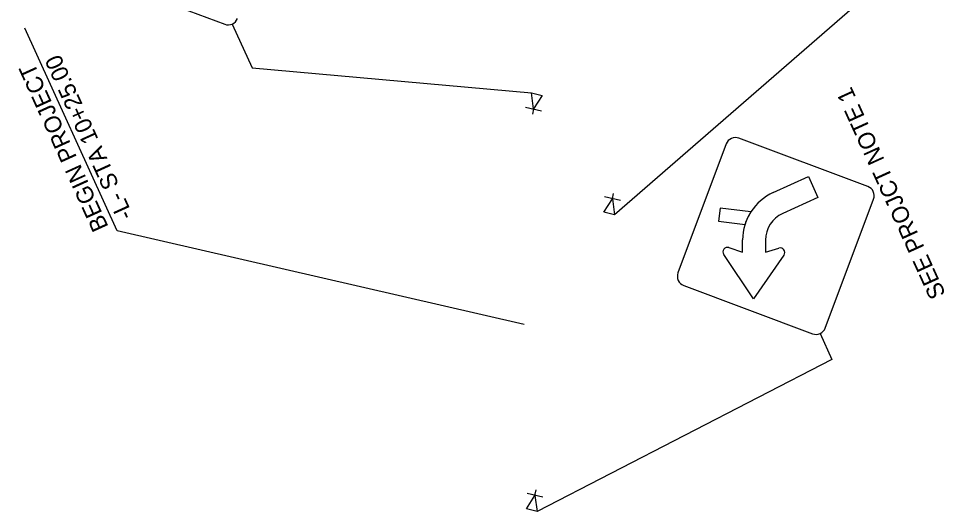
# Model space of a CAD drawing. Extents: x 2096093 to 2099001, y 683546 to 685907.
# Drawn here: x 2096431.2 to 2096816.5, y 683545.9 to 683750.8 of the extents above; entities that cross this region are included whole.
import ezdxf

# ---------------------------------------------------------------- set-up
doc = ezdxf.new("R2010")
doc.units = 0
for name, color, linetype in [('Default', 7, 'Continuous'), ('Exist Sign E Curve Left CELL', 7, 'Continuous'), ('Prop Horizontal Alignment Station Label', 7, 'Continuous')]:
    doc.layers.add(name, color=color, linetype=linetype)

msp = doc.modelspace()

# ---------------------------------------------------------------- linework, layer by layer
at = {"layer": 'Default'}
for p, q in [((2096645.33, 683713.23), (2096644.42, 683719.91)), ((2096644.42, 683719.91), (2096648.87, 683718.86)), ((2096648.87, 683718.86), (2096645.33, 683713.23)), ((2096641.99, 683714.02), (2096648.61, 683712.46)), ((2096645.33, 683713.23), (2096644.8, 683710.98)), ((2096678.06, 683675.89), (2096678.59, 683678.14)), ((2096674.52, 683670.25), (2096678.06, 683675.89)), ((2096681.4, 683675.11), (2096674.77, 683676.66)), ((2096678.06, 683675.89), (2096678.98, 683669.21)), ((2096678.98, 683669.21), (2096674.52, 683670.25)), ((2096764.44, 683619.87), (2096769.35, 683609.07)), ((2096645.88, 683552.62), (2096646.4, 683554.87)), ((2096642.34, 683546.98), (2096645.88, 683552.62)), ((2096649.22, 683551.84), (2096642.59, 683553.38)), ((2096645.88, 683552.62), (2096646.79, 683545.94)), ((2096646.79, 683545.94), (2096642.34, 683546.98))]:
    msp.add_line(p, q, dxfattribs=at)
for points in [[(2096775.78, 683769.09), (2096780.98, 683757.66), (2096678.98, 683669.21)], [(2096520.03, 683748.5), (2096528.29, 683730.35), (2096644.42, 683719.91)], [(2096769.35, 683609.07), (2096769.35, 683609.07), (2096646.79, 683545.94)]]:
    msp.add_lwpolyline(points, dxfattribs=at)
at = {"layer": 'Exist Sign E Curve Left CELL'}
for p, q in [((2096463.32, 683768.48), (2096516.91, 683748.4)), ((2096784.26, 683680.99), (2096730.67, 683701.07)), ((2096725.42, 683698.69), (2096705.34, 683645.1)), ((2096763.49, 683676.41), (2096748.87, 683669.77)), ((2096763.49, 683676.41), (2096748.87, 683669.77)), ((2096763.49, 683676.41), (2096748.87, 683669.77)), ((2096766.57, 683622.15), (2096786.65, 683675.74)), ((2096707.73, 683639.85), (2096761.32, 683619.76))]:
    msp.add_line(p, q, dxfattribs=at)
for points in [[(2096744.93, 683678.44), (2096759.54, 683685.08), (2096763.49, 683676.41)], [(2096744.93, 683678.44), (2096759.54, 683685.08), (2096763.49, 683676.41)], [(2096744.93, 683678.44), (2096759.54, 683685.08), (2096763.49, 683676.41)], [(2096735.65, 683670.43), (2096722.83, 683672.02), (2096722.16, 683666.62), (2096733.2, 683665.24)], [(2096726.53, 683655.59), (2096732.13, 683653.76), (2096732.18, 683658.81)], [(2096726.53, 683655.59), (2096732.13, 683653.76), (2096732.18, 683658.81)], [(2096726.53, 683655.59), (2096732.13, 683653.76), (2096732.18, 683658.81)], [(2096741.7, 683658.73), (2096741.66, 683653.68), (2096747.28, 683655.41)], [(2096741.7, 683658.73), (2096741.66, 683653.68), (2096747.28, 683655.41)], [(2096741.7, 683658.73), (2096741.66, 683653.68), (2096747.28, 683655.41)], [(2096749.41, 683652.5), (2096736.73, 683634.35), (2096724.36, 683652.71)], [(2096749.41, 683652.5), (2096736.73, 683634.35), (2096724.36, 683652.71)], [(2096749.41, 683652.5), (2096736.73, 683634.35), (2096724.36, 683652.71)]]:
    msp.add_lwpolyline(points, dxfattribs=at)
for centre, radius, start, end in [((2096518.34, 683752.22), 4.08, 249.458, 339.458), ((2096729.24, 683697.25), 4.08, 69.458, 159.458), ((2096782.83, 683677.17), 4.08, 339.458, 69.458), ((2096753.94, 683658.62), 21.77, 147.1671, 162.2946), ((2096709.16, 683643.66), 4.08, 159.458, 249.458), ((2096762.75, 683623.58), 4.08, 249.458, 339.458)]:
    msp.add_arc(centre, radius, start, end, dxfattribs=at)
for centre, major_axis, start_param, end_param in [((2096753.94, 683658.62), (-19.82, -9.01), 4.712389, 5.847944), ((2096753.94, 683658.62), (-19.82, -9.01), 4.712389, 5.847944), ((2096753.94, 683658.62), (-19.82, -9.01), 4.712389, 5.847944), ((2096753.94, 683658.62), (-11.15, -5.07), 4.712389, 5.847944), ((2096753.94, 683658.62), (-11.15, -5.07), 4.712389, 5.847944), ((2096753.94, 683658.62), (-11.15, -5.07), 4.712389, 5.847944), ((2096725.94, 683653.78), (-1.73, -0.79), 3.969953, 6.449197), ((2096725.94, 683653.78), (-1.73, -0.79), 3.969953, 6.449197), ((2096725.94, 683653.78), (-1.73, -0.79), 3.969953, 6.449197), ((2096747.85, 683653.6), (1.73, 0.79), 5.246691, 7.725935), ((2096747.85, 683653.6), (1.73, 0.79), 5.246691, 7.725935), ((2096747.85, 683653.6), (1.73, 0.79), 5.246691, 7.725935)]:
    msp.add_ellipse(centre, major_axis=major_axis, ratio=0.999989, start_param=start_param, end_param=end_param, dxfattribs=at)
at = {"layer": 'Prop Horizontal Alignment Station Label'}
for p, q in [((2096472.13, 683662.58), (2096433.81, 683746.84)), ((2096641.33, 683623.7), (2096472.13, 683662.58))]:
    msp.add_line(p, q, dxfattribs=at)

# ---------------------------------------------------------------- texts
at = {"layer": 'Default'}
msp.add_text('SEE PROJCT NOTE 1', height=7, rotation=114.4888, dxfattribs=at).set_placement((2096816.77, 683636.18))
at = {"layer": 'Prop Horizontal Alignment Station Label'}
for s, p in [('-L- STA 10+25.00', (2096478.96, 683668.9)), ('BEGIN PROJECT', (2096468.7, 683664.24))]:
    msp.add_text(s, height=7, rotation=114.458, dxfattribs=at).set_placement(p)

doc.saveas('drawing.dxf')
